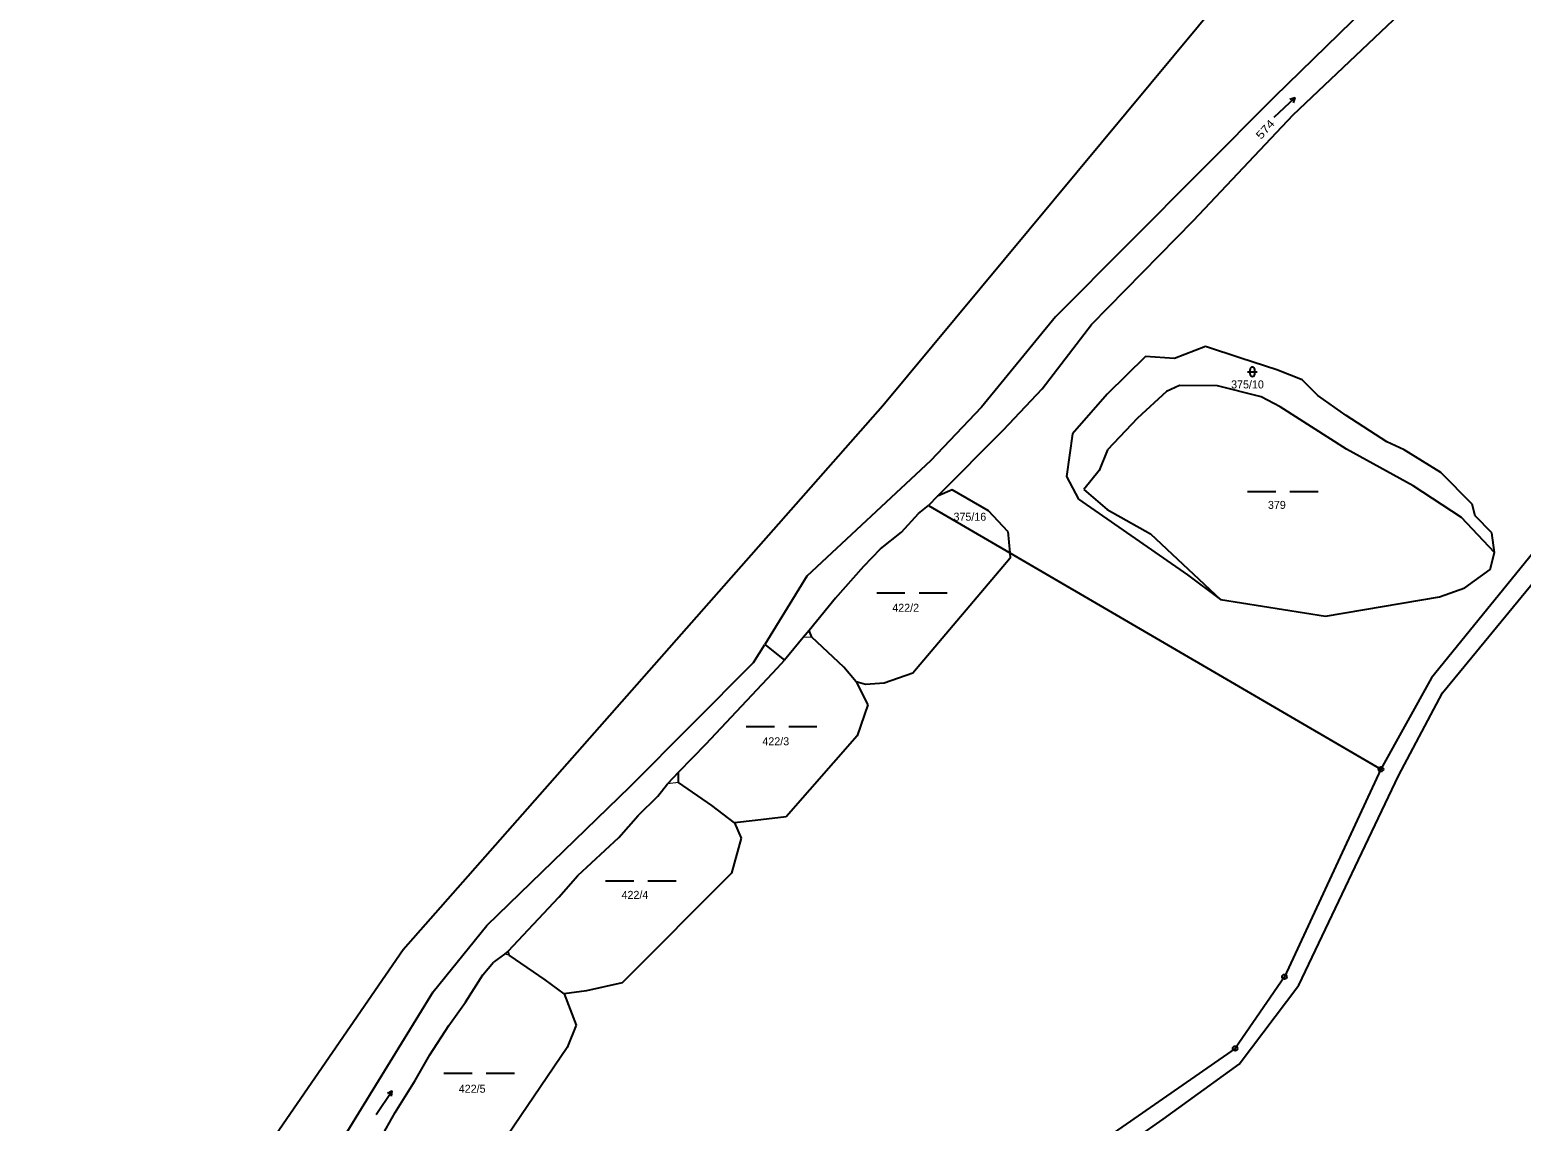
# Model space of a CAD drawing. Extents: x -885985 to -883535, y -1030025 to -1027941.
# Drawn here: x -884595.8 to -884278.9, y -1029082.6 to -1028850.6 of the extents above; entities that cross this region are included whole.
import ezdxf
from ezdxf.enums import TextEntityAlignment as Align

# ---------------------------------------------------------------- set-up
doc = ezdxf.new("R2010")
doc.units = 0
doc.header["$LTSCALE"] = 0.68
for name, color, linetype, lineweight in [('1', 7, 'Continuous', 25), ('3', 7, 'Continuous', 25), ('4', 7, 'Continuous', 13), ('8', 7, 'Continuous', 25)]:
    doc.layers.add(name, color=color, linetype=linetype, lineweight=lineweight)
doc.layers.add('2', color=7, linetype='Continuous')

msp = doc.modelspace()

# ---------------------------------------------------------------- linework, layer by layer
at = {"layer": '1'}
for p, q in [((-884315.38, -1028811.03), (-884414.54, -1028930.55)), ((-884304.65, -1028838.78), (-884331.36, -1028864.88)), ((-884327.4, -1028868.7), (-884299.72, -1028842.45)), ((-884331.36, -1028864.88), (-884377.9, -1028911.59)), ((-884348.54, -1028891.14), (-884327.4, -1028868.7)), ((-884370.2, -1028913.22), (-884348.54, -1028891.14)), ((-884377.9, -1028911.59), (-884393.6, -1028930.84)), ((-884380.69, -1028926.95), (-884370.2, -1028913.22)), ((-884358.74, -1028920.01), (-884366.91, -1028928.07)), ((-884352.55, -1028920.44), (-884358.74, -1028920.01)), ((-884346.03, -1028917.92), (-884352.55, -1028920.44)), ((-884338.52, -1028920.41), (-884346.03, -1028917.92)), ((-884330.85, -1028922.89), (-884338.52, -1028920.41)), ((-884325.49, -1028924.99), (-884330.85, -1028922.89)), ((-884388.89, -1028935.66), (-884380.69, -1028926.95)), ((-884351.55, -1028926.19), (-884354.26, -1028927.47)), ((-884343.45, -1028926.25), (-884351.55, -1028926.19)), ((-884334.15, -1028928.62), (-884343.45, -1028926.25)), ((-884322.12, -1028928.33), (-884325.49, -1028924.99)), ((-884366.91, -1028928.07), (-884374.28, -1028936.51)), ((-884354.26, -1028927.47), (-884360.44, -1028933.18)), ((-884330.13, -1028930.77), (-884334.15, -1028928.62)), ((-884316.1, -1028932.56), (-884322.12, -1028928.33)), ((-884414.54, -1028930.55), (-884516.49, -1029046.16)), ((-884393.6, -1028930.84), (-884404.41, -1028942.21)), ((-884360.44, -1028933.18), (-884366.85, -1028939.91)), ((-884316.05, -1028939.75), (-884330.13, -1028930.77)), ((-884307.49, -1028938.16), (-884316.1, -1028932.56)), ((-884388.89, -1028935.66), (-884402.91, -1028949.75)), ((-884374.28, -1028936.51), (-884375.51, -1028945.54)), ((-884301.84, -1028947.51), (-884316.05, -1028939.75)), ((-884303.82, -1028939.88), (-884307.49, -1028938.16)), ((-884404.41, -1028942.21), (-884430.69, -1028966.76)), ((-884366.85, -1028939.91), (-884368.59, -1028944.24)), ((-884295.99, -1028944.73), (-884303.82, -1028939.88)), ((-884375.51, -1028945.54), (-884372.99, -1028950.39)), ((-884368.59, -1028944.24), (-884371.88, -1028948.34)), ((-884289.31, -1028951.46), (-884295.99, -1028944.73)), ((-884399.84, -1028948.41), (-884402.91, -1028949.75)), ((-884392.09, -1028952.81), (-884399.84, -1028948.41)), ((-884371.88, -1028948.34), (-884366.89, -1028952.54)), ((-884291.59, -1028954.29), (-884301.84, -1028947.51)), ((-884406.99, -1028953.41), (-884404.87, -1028951.71)), ((-884402.91, -1028949.75), (-884404.87, -1028951.71)), ((-884404.87, -1028951.71), (-884387.59, -1028961.78)), ((-884372.99, -1028950.39), (-884349.79, -1028966.45)), ((-884366.89, -1028952.54), (-884357.71, -1028957.74)), ((-884288.68, -1028953.92), (-884289.31, -1028951.46)), ((-884410.62, -1028957.36), (-884406.99, -1028953.41)), ((-884388.02, -1028957.2), (-884392.09, -1028952.81)), ((-884284.6, -1028961.73), (-884291.59, -1028954.29)), ((-884285.14, -1028957.52), (-884288.68, -1028953.92)), ((-884415.05, -1028960.93), (-884410.62, -1028957.36)), ((-884388.02, -1028957.2), (-884387.59, -1028961.78)), ((-884357.71, -1028957.74), (-884342.83, -1028971.68)), ((-884272.75, -1028957.32), (-884297.96, -1028988.3)), ((-884284.6, -1028961.73), (-884285.14, -1028957.52)), ((-884418.56, -1028964.61), (-884415.05, -1028960.93)), ((-884387.59, -1028961.78), (-884387.48, -1028962.91)), ((-884387.59, -1028961.78), (-884308.71, -1029007.76)), ((-884295.62, -1028991.54), (-884271.44, -1028962.02)), ((-884285.54, -1028965.31), (-884284.6, -1028961.73)), ((-884424.6, -1028971.39), (-884418.56, -1028964.61)), ((-884387.48, -1028962.91), (-884408.16, -1028987.33)), ((-884430.69, -1028966.76), (-884439.62, -1028981.22)), ((-884349.79, -1028966.45), (-884342.83, -1028971.68)), ((-884290.89, -1028969.22), (-884285.54, -1028965.31)), ((-884424.6, -1028971.39), (-884430.22, -1028978.24)), ((-884320.52, -1028975.22), (-884296.28, -1028971.15)), ((-884296.28, -1028971.15), (-884290.89, -1028969.22)), ((-884342.83, -1028971.68), (-884320.52, -1028975.22)), ((-884431.47, -1028979.76), (-884435.41, -1028984.56)), ((-884430.22, -1028978.24), (-884431.47, -1028979.76)), ((-884429.61, -1028979.72), (-884430.22, -1028978.24)), ((-884422.86, -1028986.04), (-884429.61, -1028979.72)), ((-884442.02, -1028985.1), (-884439.62, -1028981.22)), ((-884439.62, -1028981.22), (-884435.41, -1028984.56)), ((-884468.24, -1029011.42), (-884442.02, -1028985.1)), ((-884452.16, -1029002.44), (-884436.91, -1028986.21)), ((-884436.91, -1028986.21), (-884435.41, -1028984.56)), ((-884420.19, -1028989.15), (-884422.86, -1028986.04)), ((-884408.16, -1028987.33), (-884414.25, -1028989.48)), ((-884420.19, -1028989.15), (-884417.73, -1028994.07)), ((-884418.22, -1028989.73), (-884420.19, -1028989.15)), ((-884414.25, -1028989.48), (-884418.22, -1028989.73)), ((-884297.96, -1028988.3), (-884308.71, -1029007.76)), ((-884304.98, -1029009.13), (-884295.62, -1028991.54)), ((-884417.73, -1028994.07), (-884419.99, -1029000.65)), ((-884452.16, -1029002.44), (-884457.95, -1029008.41)), ((-884419.99, -1029000.65), (-884435.1, -1029017.87)), ((-884457.95, -1029008.41), (-884460.32, -1029010.85)), ((-884457.98, -1029010.6), (-884457.95, -1029008.41)), ((-884308.71, -1029007.76), (-884329.22, -1029051.86)), ((-884326.2, -1029053.64), (-884304.98, -1029009.13)), ((-884498.71, -1029040.97), (-884468.24, -1029011.42)), ((-884462.38, -1029013.46), (-884460.32, -1029010.85)), ((-884450.9, -1029015.45), (-884457.98, -1029010.6)), ((-884466.54, -1029017.59), (-884462.38, -1029013.46)), ((-884446.05, -1029019.16), (-884450.9, -1029015.45)), ((-884470.66, -1029022.27), (-884466.54, -1029017.59)), ((-884441.65, -1029018.68), (-884446.05, -1029019.16)), ((-884435.1, -1029017.87), (-884441.65, -1029018.68)), ((-884446.05, -1029019.16), (-884444.68, -1029022.41)), ((-884479.34, -1029030.37), (-884470.66, -1029022.27)), ((-884444.68, -1029022.41), (-884446.68, -1029029.81)), ((-884483.42, -1029034.97), (-884479.34, -1029030.37)), ((-884446.68, -1029029.81), (-884469.91, -1029053.15)), ((-884494.18, -1029046.45), (-884483.42, -1029034.97)), ((-884510.06, -1029055.09), (-884498.71, -1029040.97)), ((-884516.49, -1029046.16), (-884595.79, -1029161.22)), ((-884494.97, -1029047.05), (-884497.25, -1029048.78)), ((-884494.18, -1029046.45), (-884494.97, -1029047.05)), ((-884493.94, -1029047.24), (-884494.18, -1029046.45)), ((-884486.29, -1029052.52), (-884493.94, -1029047.24)), ((-884499.51, -1029051.46), (-884497.25, -1029048.78)), ((-884503.24, -1029057.25), (-884499.51, -1029051.46)), ((-884482.23, -1029055.52), (-884486.29, -1029052.52)), ((-884469.91, -1029053.15), (-884477.49, -1029054.82)), ((-884329.22, -1029051.86), (-884339.7, -1029067.1)), ((-884338.86, -1029070.4), (-884326.2, -1029053.64)), ((-884535.09, -1029095.66), (-884510.06, -1029055.09)), ((-884477.49, -1029054.82), (-884482.23, -1029055.52)), ((-884482.23, -1029055.52), (-884479.68, -1029062.12)), ((-884506.79, -1029062.2), (-884503.24, -1029057.25)), ((-884510.78, -1029068.42), (-884506.79, -1029062.2)), ((-884479.68, -1029062.12), (-884481.63, -1029066.87)), ((-884513.93, -1029073.88), (-884510.78, -1029068.42)), ((-884481.63, -1029066.87), (-884502.09, -1029097.07)), ((-884339.7, -1029067.1), (-884386.02, -1029099.23)), ((-884355.02, -1029082.12), (-884338.86, -1029070.4)), ((-884518.18, -1029080.73), (-884513.93, -1029073.88)), ((-884524.11, -1029091.25), (-884518.18, -1029080.73)), ((-884384.8, -1029103.02), (-884355.02, -1029082.12))]:
    msp.add_line(p, q, dxfattribs=at)
at = {"layer": '3'}
for p, q in [((-884327.018, -1028865.099), (-884327.39, -1028866.132)), ((-884337.041, -1028923.291), (-884335.039, -1028923.291)), ((-884336.541, -1028922.791), (-884336.541, -1028923.792)), ((-884335.539, -1028923.792), (-884335.539, -1028922.791)), ((-884337.059, -1028948.73), (-884331.059, -1028948.73)), ((-884328.059, -1028948.73), (-884322.059, -1028948.73)), ((-884415.849, -1028970.24), (-884409.849, -1028970.24)), ((-884406.849, -1028970.24), (-884400.849, -1028970.24)), ((-884443.559, -1028998.67), (-884437.559, -1028998.67)), ((-884434.559, -1028998.67), (-884428.559, -1028998.67)), ((-884473.489, -1029031.45), (-884467.489, -1029031.45)), ((-884464.489, -1029031.45), (-884458.489, -1029031.45)), ((-884507.799, -1029072.36), (-884501.799, -1029072.36)), ((-884498.799, -1029072.36), (-884492.799, -1029072.36)), ((-884518.856, -1029076.163), (-884518.986, -1029077.254))]:
    msp.add_line(p, q, dxfattribs=at)
for points in [[(-884331.406, -1028869.191), (-884327.018, -1028865.099), (-884328.074, -1028865.398)], [(-884522.211, -1029081.138), (-884518.856, -1029076.163), (-884519.818, -1029076.693)]]:
    msp.add_lwpolyline(points, dxfattribs=at)
for centre, start, end in [((-884336.04, -1028922.7909), 0, 180), ((-884336.04, -1028923.7909), 180, 359.98789)]:
    msp.add_arc(centre, 0.5, start, end, dxfattribs=at)
at = {"layer": '4'}
for p, q in [((-884429.61, -1028979.72), (-884431.47, -1028979.76)), ((-884457.98, -1029010.6), (-884460.32, -1029010.85)), ((-884493.94, -1029047.24), (-884494.97, -1029047.05))]:
    msp.add_line(p, q, dxfattribs=at)
at = {"layer": '8'}
for centre, radius in [((-884308.71, -1029007.7599), 0.5), ((-884308.71, -1029007.7599), 0.0303), ((-884329.22, -1029051.8599), 0.5), ((-884329.22, -1029051.8599), 0.0303), ((-884339.7, -1029067.0999), 0.5), ((-884339.7, -1029067.0999), 0.0303)]:
    msp.add_circle(centre, radius, dxfattribs=at)

# ---------------------------------------------------------------- texts
at = {"layer": '2', "width": 1.2}
msp.add_text('574', height=1.7, rotation=48, dxfattribs=at).set_placement((-884334.194, -1028874.034))
at = {"layer": '2'}
for s, p in [('375/10', (-884340.55, -1028926.825)), ('379', (-884332.73, -1028952.435))]:
    msp.add_text(s, height=1.7, dxfattribs=at).set_placement(p)
for s, p in [('375/16', (-884396.06, -1028954.945)), ('422/2', (-884409.7, -1028974.295)), ('422/3', (-884437.3, -1029002.665)), ('422/4', (-884467.22, -1029035.305)), ('422/5', (-884501.81, -1029076.505))]:
    msp.add_text(s, height=1.7, dxfattribs=at).set_placement(p, align=Align.CENTER)

doc.saveas('drawing.dxf')
